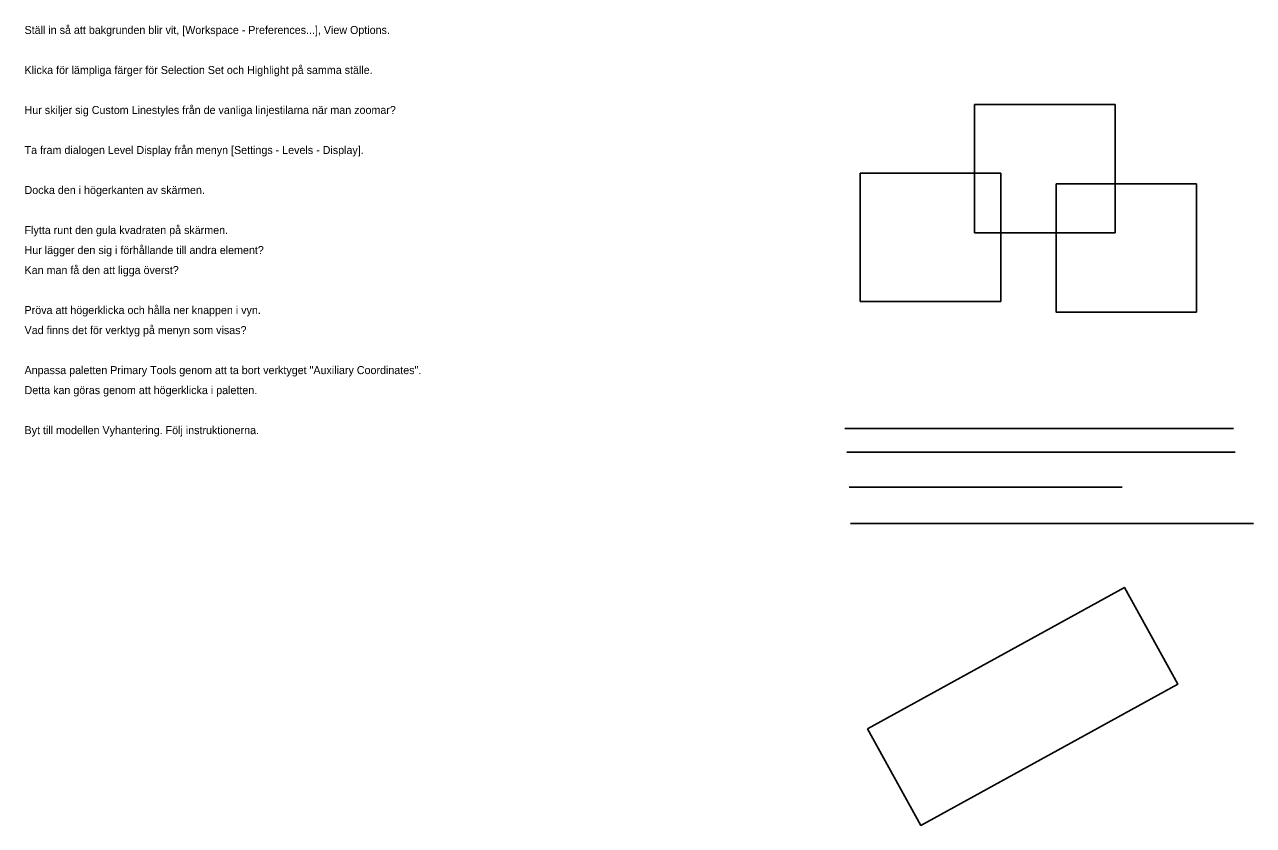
# Model space of a CAD drawing. Extents: x 1517666.1 to 1517752.4, y 6495328.8 to 6495385.
import ezdxf

# ---------------------------------------------------------------- set-up
doc = ezdxf.new("R2010")
doc.units = 0
doc.layers.add('Instruktioner', color=7, linetype='Continuous')
doc.layers.add('Lager 1', color=7, linetype='Continuous')

msp = doc.modelspace()

# ---------------------------------------------------------------- linework, layer by layer
at = {"layer": 'Lager 1'}
for p, q in [((1517723.752, 6495356.646), (1517751.038, 6495356.646)), ((1517723.888, 6495354.986), (1517751.174, 6495354.986)), ((1517724.041, 6495352.525), (1517743.218, 6495352.525)), ((1517724.143, 6495349.974), (1517752.449, 6495349.974))]:
    msp.add_line(p, q, dxfattribs=at)
for points in [[(1517732.855, 6495379.414), (1517742.724, 6495379.414), (1517742.724, 6495370.403), (1517732.855, 6495370.403)], [(1517724.824, 6495374.59), (1517734.693, 6495374.59), (1517734.693, 6495365.578), (1517724.824, 6495365.578)], [(1517738.581, 6495373.841), (1517748.449, 6495373.841), (1517748.449, 6495364.83), (1517738.581, 6495364.83)], [(1517725.345, 6495335.555), (1517729.085, 6495328.757), (1517747.128, 6495338.683), (1517743.388, 6495345.482)]]:
    msp.add_lwpolyline(points, close=True, dxfattribs=at)

# ---------------------------------------------------------------- texts
at = {"layer": 'Instruktioner'}
for s, p in [('Ställ in så att bakgrunden blir vit, [Workspace - Preferences...], View Options.', (1517666.113, 6495384.379)), ('Klicka för lämpliga färger för Selection Set och Highlight på samma ställe.', (1517666.113, 6495381.567)), ('Hur skiljer sig Custom Linestyles från de vanliga linjestilarna när man zoomar?', (1517666.113, 6495378.755)), ('Ta fram dialogen Level Display från menyn [Settings - Levels - Display].', (1517666.113, 6495375.942)), ('Docka den i högerkanten av skärmen.', (1517666.113, 6495373.13)), ('Flytta runt den gula kvadraten på skärmen. ', (1517666.113, 6495370.317)), ('Hur lägger den sig i förhållande till andra element?', (1517666.113, 6495368.911)), ('Kan man få den att ligga överst?', (1517666.113, 6495367.505)), ('Pröva att högerklicka och hålla ner knappen i vyn.', (1517666.113, 6495364.693)), ('Vad finns det för verktyg på menyn som visas?', (1517666.113, 6495363.286)), ('Anpassa paletten Primary Tools genom att ta bort verktyget "Auxiliary Coordinates".', (1517666.113, 6495360.474)), ('Detta kan göras genom att högerklicka i paletten.', (1517666.113, 6495359.068)), ('Byt till modellen Vyhantering. Följ instruktionerna.', (1517666.113, 6495356.255))]:
    msp.add_text(s, height=0.56248, dxfattribs=at).set_placement(p)

doc.saveas('drawing.dxf')
